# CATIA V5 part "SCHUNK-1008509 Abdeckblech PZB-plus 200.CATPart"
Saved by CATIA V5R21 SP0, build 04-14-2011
Part number: SCHUNK-1008509 Abdeckblech PZB-plus 200
Property "ParasolidId": 21
Property "PSOL_INSTNR": 6
Bounding box of the stored display mesh (mm): x -55.3 to 58, y 0 to 1.5, z -58 to 58
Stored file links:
  C:\Users\MIRCEA\Desktop\PRRO\CATIAV5\SCHUNK-1008509 Abdeckblech PZB-plus 200.CATPart
  C:\Program Files (x86)\Dassault Systemes\B21\intel_a\startup\materials\French\Catalog.CATMaterial
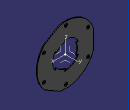
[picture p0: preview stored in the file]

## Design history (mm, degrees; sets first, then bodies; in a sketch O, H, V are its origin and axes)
AxisSystem1: origin (0, 0, 0), X (1, 0, 0), Y (0, 1, 0), Z (0, 0, 1)
Body1 "SCHUNK-1008509 Abdeckblech PZB-plus 200(1)" (main body)
  Solid1: solid without history
  Sketch1 on zx-plane, origin (0, 0, 0), H (-1, 0, 0), V (0, 0, 1)
    point P1 (0, 0)
    coincidence: P1 O
  Sketch2 on yz-plane, origin (0, 0, 0), H (0, 1, 0), V (0, 0, 1)
    line L1 (0, 0) -> (40, 0)
    length L1 = 40
    horizontal: L1 H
